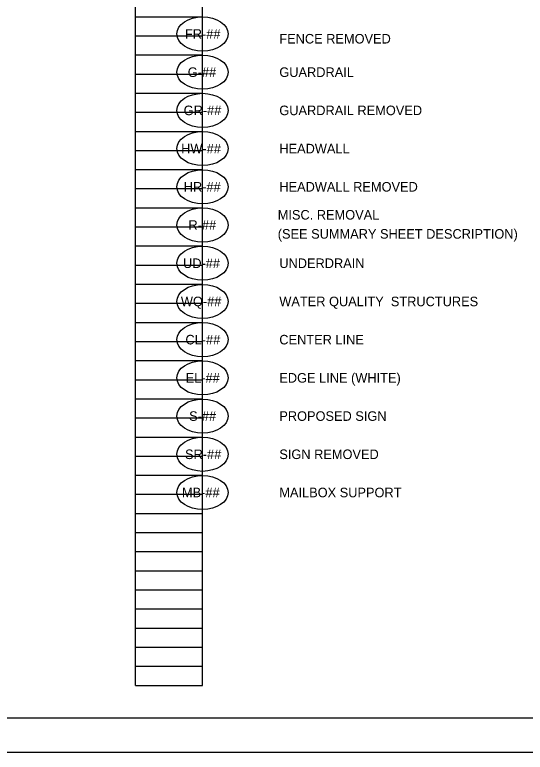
# Model space of a CAD drawing. Extents: x -8.3 to 34, y 0 to 22.
# Drawn here: x 21.91 to 29.39, y 0 to 10.81 of the extents above; entities that cross this region are included whole.
import ezdxf

# ---------------------------------------------------------------- set-up
doc = ezdxf.new("R2010")
doc.units = 0
for name, color, linetype in [('SH_Border', 7, 'Continuous'), ('SH_Cut_Line', 7, 'Continuous'), ('SH_Data', 7, 'Continuous'), ('SH_Text', 7, 'Continuous')]:
    doc.layers.add(name, color=color, linetype=linetype)

msp = doc.modelspace()

# ---------------------------------------------------------------- linework, layer by layer
at = {"layer": 'SH_Border'}
msp.add_lwpolyline([(1.5, 21.5), (33.5, 21.5), (33.5, 0.5), (1.5, 0.5)], close=True, dxfattribs=at)
at = {"layer": 'SH_Cut_Line'}
msp.add_lwpolyline([(0, 0), (34, 0), (34, 22), (0, 22)], close=True, dxfattribs=at)
at = {"layer": 'SH_Data'}
for p, q in [((23.68, 0.98), (23.68, 21.14)), ((24.66, 0.98), (24.66, 21.14)), ((23.68, 10.78), (24.66, 10.78)), ((23.68, 10.5), (24.66, 10.5)), ((23.68, 10.22), (24.66, 10.22)), ((23.68, 9.94), (24.66, 9.94)), ((23.68, 9.66), (24.66, 9.66)), ((23.68, 9.38), (24.66, 9.38)), ((23.68, 9.1), (24.66, 9.1)), ((23.68, 8.82), (24.66, 8.82)), ((23.68, 8.54), (24.66, 8.54)), ((23.68, 8.26), (24.66, 8.26)), ((23.68, 7.98), (24.66, 7.98)), ((23.68, 7.7), (24.66, 7.7)), ((23.68, 7.42), (24.66, 7.42)), ((23.68, 7.14), (24.66, 7.14)), ((23.68, 6.86), (24.66, 6.86)), ((23.68, 6.58), (24.66, 6.58)), ((23.68, 6.3), (24.66, 6.3)), ((23.68, 6.02), (24.66, 6.02)), ((23.68, 5.74), (24.66, 5.74)), ((23.68, 5.46), (24.66, 5.46)), ((23.68, 5.18), (24.66, 5.18)), ((23.68, 4.9), (24.66, 4.9)), ((23.68, 4.62), (24.66, 4.62)), ((23.68, 4.34), (24.66, 4.34)), ((23.68, 4.06), (24.66, 4.06)), ((23.68, 3.78), (24.66, 3.78)), ((23.68, 3.5), (24.66, 3.5)), ((23.68, 3.22), (24.66, 3.22)), ((23.68, 2.94), (24.66, 2.94)), ((23.68, 2.66), (24.66, 2.66)), ((23.68, 2.38), (24.66, 2.38)), ((23.68, 2.1), (24.66, 2.1)), ((23.68, 1.82), (24.66, 1.82)), ((23.68, 1.54), (24.66, 1.54)), ((23.68, 1.26), (24.66, 1.26)), ((23.68, 0.98), (24.66, 0.98))]:
    msp.add_line(p, q, dxfattribs=at)
at = {"layer": 'SH_Text'}
for centre in [(24.66, 10.527), (24.66, 9.967), (24.66, 9.407), (24.66, 8.847), (24.66, 8.287), (24.66, 7.727), (24.66, 7.167), (24.66, 6.607), (24.66, 6.047), (24.66, 5.487), (24.66, 4.927), (24.66, 4.367), (24.66, 3.807)]:
    msp.add_ellipse(centre, major_axis=(0.375, 0), ratio=0.666667, dxfattribs=at)

# ---------------------------------------------------------------- texts
for s, p in [('FR-##', (24.403, 10.457)), ('FENCE REMOVED', (25.785, 10.387)), ('G-##', (24.444, 9.897)), ('GUARDRAIL', (25.785, 9.897)), ('GR-##', (24.384, 9.337)), ('GUARDRAIL REMOVED', (25.785, 9.337)), ('HW-##', (24.347, 8.777)), ('HEADWALL', (25.785, 8.777)), ('HR-##', (24.385, 8.217)), ('HEADWALL REMOVED', (25.785, 8.217)), ('MISC. REMOVAL', (25.762, 7.807)), ('R-##', (24.454, 7.657)), ('(SEE SUMMARY SHEET DESCRIPTION)', (25.762, 7.527)), ('UD-##', (24.375, 7.097)), ('UNDERDRAIN', (25.785, 7.097)), ('WQ-##', (24.343, 6.537)), ('WATER QUALITY  STRUCTURES', (25.785, 6.537)), ('CL-##', (24.41, 5.977)), ('CENTER LINE', (25.785, 5.977)), ('EL-##', (24.413, 5.417)), ('EDGE LINE (WHITE)', (25.785, 5.417)), ('S-##', (24.464, 4.857)), ('PROPOSED SIGN', (25.785, 4.857)), ('SR-##', (24.404, 4.297)), ('SIGN REMOVED', (25.785, 4.297)), ('MB-##', (24.359, 3.737)), ('MAILBOX SUPPORT', (25.785, 3.737))]:
    msp.add_text(s, height=0.14, dxfattribs=at).set_placement(p)

doc.saveas('drawing.dxf')
